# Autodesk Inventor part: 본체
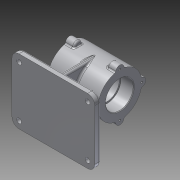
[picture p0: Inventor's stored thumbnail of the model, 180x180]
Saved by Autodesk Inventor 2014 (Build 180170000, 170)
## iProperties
Created: 2015-12
Part Number: 본체
Material: 알루미늄 6061
Document SubType Name: Modeling
Designer: test_25
Density: 2.71 g/cm^3
Appearance: 알루미늄 - 평지
Mass: 1166.69 g
Surface Area: 816.445 cm^2
Volume: 430.512 cm^3
Author: test_25
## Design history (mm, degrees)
sketch "스케치3"
  geometry: L1 (-42.5, 37)-(42.5, 37); L2 (42.5, 37)-(42.5, 23.5); L3 (42.5, 23.5)-(20.5, 23.5); L4 (20.5, 23.5)-(20.5, 21); L5 (20.5, 21)-(-20.5, 21); L6 (-20.5, 21)-(-20.5, 23.5); L7 (-20.5, 23.5)-(-42.5, 23.5); L8 (-42.5, 23.5)-(-42.5, 37); L9 (-42.5, 0)-(42.5, 0); 2 further points
  constraints: 18 end point, 4 horizontal, 3 vertical, 2 perpendicular, 2 vertical alignment, 1 coincident, 1 midpoint
  dimensions: "d0" = 85 distance of L1.start L1.end; "d1" = 22 distance of L6.end L7.end; "d2" = 41 distance of L4.end L5.end; "d3" = 47 diameter of L7 L9; "d4" = 42 diameter of L5 L9; "d5" = 47 diameter of L3 L9; "d6" = 74 diameter of L1 L9
revolve "회전1" sketch "스케치3" stored, may be unused: angle "d7" = 90 deg
node "작업 평면1"
sketch "스케치4"
  geometry: L1 (-68, 55)-(48, 55); L2 (60, 43)-(60, -43); L3 (48, -55)-(-68, -55); L4 (-80, -43)-(-80, 43); A1 r 12 centre (-68, 43) between (-68, 55) and (-80, 43); A2 r 12 centre (-68, -43) between (-80, -43) and (-68, -55); A3 r 12 centre (48, -43) between (48, -55) and (60, -43); A4 r 12 centre (48, 43) between (60, 43) and (48, 55); 4 further points
  constraints: 8 end point, 8 point on circle, 8 tangent, 6 point on line, 4 centre point, 3 equal radius, 2 parallel, 1 horizontal, 1 perpendicular
  dimensions: "d9" = 140 distance of point (-80, 55) point (60, 55); "d10" = 110 distance of point (60, 55) point (60, -55); "d11" = 80 distance from line of L4 point (0, 0); "d12" = 55 distance from line of L1 point (0, 0); "d13" = 12 radius of A1
extrude "돌출1" join sketch "스케치4" distance "d14" = 10; taper "d15" = 0 deg
sketch "스케치6"
  geometry: L1 (25, -6)-(-25, -6); L2 (-25, -6)-(-25, 6); L3 (-25, 6)-(25, 6); L4 (25, 6)-(25, -6); L5 (4, -37)-(-4, -37); L6 (-4, -37)-(-4, 37); L7 (-4, 37)-(4, 37); L8 (4, 37)-(4, -37); L9 (4, -37)-(-4, 37); L10 (25, -6)-(-25, 6); 2 further points
  constraints: 20 end point, 4 parallel, 2 horizontal, 2 midpoint, 2 perpendicular, 1 coincident
  dimensions: "d21" = 50 distance of L2.end L3.end; "d22" = 8 distance of L6.end L7.end; "d23" = 12 distance of L1.end L2.end; "d26" = 74 distance of L5.end L6.end
extrude "돌출2" join sketch "스케치6" stored distance "d27" = 10; taper "d28" = 0 deg
sketch "스케치7"
  geometry: C1 r 7 at (0, 37); 1 further point
  constraints: 2 vertical alignment, 1 centre point, 1 other
  dimensions: "d31" = 14 diameter of C1
extrude "돌출4" join sketch "스케치7" distance "d32" = 15; taper "d33" = 0 deg
sketch "스케치13"
  geometry: L1 (-27.5, 37)-(42.5, 37) reference; 1 further point
sketch "스케치14"
  geometry: L1 (-27.5, 37)-(42.5, 37) reference; L2 (-27.5, 37)-(-27.5, 44); L3 (-27.5, 44)-(-30.048, 44); L4 (-30.048, 44)-(-27.5, 37); L5 (-42.5, 44)-(-27.5, 44) reference; L6 (-88, 0)-(108, 0) reference; 1 further point
  constraints: 6 end point, 2 perpendicular, 1 collinear
  dimensions: "d73" = 110 deg angle of L1 L4
revolve "회전2" stored, may be unused: angle "d74" = 20 deg
revolve "회전3" stored, may be unused: angle "d75" = 20 deg
sketch "스케치8"
  geometry: 2 further points
  constraints: 1 vertical alignment
  dimensions: "d34" = 37 distance of point (0, 0) point (0, -37)
hole "구멍1" sketch "스케치8" at (0, 0) diameter "d35" = 3.242; stored, may be unused: countersink angle "d39" = 90 deg, drill point angle "d41" = 118 deg; dims "d36" = 9, "d37" = 4, "d38" = 2, "d40" = 11
sketch "스케치9"
  geometry: C1 r 4 at (-48, 43); C2 r 4 at (68, 43); C3 r 4 at (68, -43); C4 r 4 at (-48, -43); A1 r 12 centre (68, 43) between (80, 43) and (68, 55) reference; A2 r 12 centre (-48, 43) between (-48, 55) and (-60, 43) reference; A3 r 12 centre (-48, -43) between (-60, -43) and (-48, -55) reference; A4 r 12 centre (68, -43) between (68, -55) and (80, -43) reference; 1 further point
  constraints: 4 centre point, 4 coincident, 3 equal radius
  dimensions: "d45" = 8 diameter of C1
extrude "돌출5" cut sketch "스케치9" stored distance "d46" = 15; taper "d47" = 0 deg
sketch "스케치17"
  geometry: L1 (68, -70)-(-48, -70) reference; L2 (-42.5, -37)-(42.5, -37) reference; L3 (-20.948, -37)-(-25, -70); 1 further point
  constraints: 2 end point, 2 point on line
  dimensions: "d94" = 97 deg angle of L1 L3; "d95" = 25 horizontal distance of point (0, 0) L3.end
feature "리브2" sketch "스케치17" dims "d96" = 1, "d97" = 12, "d98" = 0, "d99" = 0, "d100" = 1, "d101" = 1
chamfer "모따기1" distance "d62" = 1; stored, may be unused: second distance "d63" = 2, angle "d64" = 45 deg
fillet "모깎기4" dims "d65" = 0.3
fillet "모깎기5" dims "d79" = 3
fillet "모깎기6" dims "d80" = 3
sketch "스케치15"
  geometry: L1 (26.163, -26.163)-(0, 0); L2 (0, 0)-(0, -37); A1 r 37 centre (0, 0) between (26.163, -26.163) and (0, -37); 1 further point
  constraints: 4 end point, 2 point on circle, 1 centre point, 1 coincident, 1 vertical
  dimensions: "d84" = 74 diameter of A1; "d86" = 45 deg angle of L2 L1
fillet "모깎기11" dims "d102" = 3
fillet "모깎기12" dims "d103" = 3
fillet "모깎기13" dims "d104" = 3
chamfer "모따기2" distance "d105" = 1; stored, may be unused: second distance "d106" = 2, angle "d107" = 45 deg
fillet "모깎기14" dims "d108" = 3
sketch "스케치18"
  geometry: L1 (0, -37)-(0, 0); L2 (0, 0)-(26.163, -26.163); A1 r 37 centre (0, 0) between (0, -37) and (26.163, -26.163); 1 further point
  constraints: 4 end point, 2 point on circle, 1 centre point, 1 coincident, 1 vertical
  dimensions: "d109" = 74 diameter of A1; "d110" = 45 deg angle of L1 L2
node "작업 평면5"
  node "작업 평면4"
sketch "스케치19"
  geometry: 2 further points
  constraints: 1 coincident, 1 other
feature "엠보싱2" sketch "스케치19" dims "d0" = 85, "d1" = 22, "d2" = 41, "d3" = 47, "d4" = 42, "d5" = 47, "d6" = 74, "d112" = 0.5, "d113" = 0
fillet "모깎기15" dims "d114" = 3
node "솔리드1"
mirror "대칭6"
pattern_circular "원형 패턴3" dims "d77" = 360 deg
mirror "대칭4"
pattern_circular "원형 패턴4" dims angle "d82" = 360 deg
mirror "대칭5"
pattern_circular "원형 패턴2" dims angle "d70" = 360 deg
mirror "대칭3"
other parameters: "d111" = 0.5
